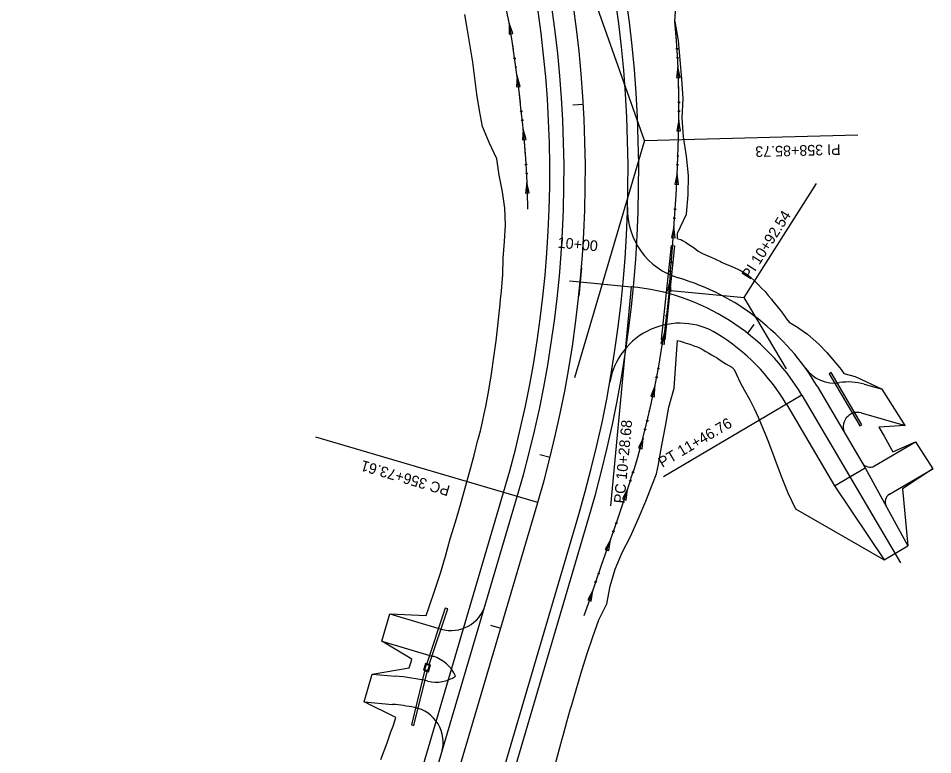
# Model space of a CAD drawing. Extents: x 948761 to 996004, y 1858548 to 1925175.
# Drawn here: x 961025 to 961539, y 1906557 to 1906971 of the extents above; entities that cross this region are included whole.
import ezdxf

# ---------------------------------------------------------------- set-up
doc = ezdxf.new("R2010")
doc.units = 0
for name, color, linetype in [('62', 7, 'Continuous'), ('R_Drainage', 7, 'Continuous'), ('R_Horz Alg', 7, 'Continuous'), ('R_Horz Alg Annot', 7, 'Continuous'), ('R_Proposed Const Limits', 7, 'Continuous'), ('R_Proposed Road', 7, 'Continuous')]:
    doc.layers.add(name, color=color, linetype=linetype)

msp = doc.modelspace()

# ---------------------------------------------------------------- linework, layer by layer
at = {"layer": '62'}
for p, q in [((961301.25, 1906967.91), (961301.21, 1906961.81)), ((961303.3, 1906962.16), (961301.25, 1906967.91)), ((961301.21, 1906961.81), (961303.3, 1906962.16)), ((961396.18, 1906943.39), (961395.38, 1906937.35)), ((961397.49, 1906937.44), (961396.18, 1906943.39)), ((961305.75, 1906938.21), (961305.45, 1906932.12)), ((961307.55, 1906932.39), (961305.75, 1906938.21)), ((961395.38, 1906937.35), (961397.49, 1906937.44)), ((961305.45, 1906932.12), (961307.55, 1906932.39)), ((961396.7, 1906913.36), (961395.53, 1906907.38)), ((961397.65, 1906907.34), (961396.7, 1906913.36)), ((961309.19, 1906908.37), (961308.71, 1906902.29)), ((961310.81, 1906902.5), (961309.19, 1906908.37)), ((961395.53, 1906907.38), (961397.65, 1906907.34)), ((961308.71, 1906902.29), (961310.81, 1906902.5)), ((961395.79, 1906883.33), (961394.42, 1906877.4)), ((961396.53, 1906877.29), (961395.79, 1906883.33)), ((961311.31, 1906878.41), (961310.48, 1906872.38)), ((961312.6, 1906872.46), (961311.31, 1906878.41)), ((961394.42, 1906877.4), (961396.53, 1906877.29)), ((961310.48, 1906872.38), (961312.6, 1906872.46)), ((961393.92, 1906853.36), (961392.5, 1906847.43)), ((961394.61, 1906847.3), (961393.92, 1906853.36)), ((961392.5, 1906847.43), (961394.61, 1906847.3)), ((961391.66, 1906823.41), (961390.25, 1906817.48)), ((961392.36, 1906817.35), (961391.66, 1906823.41)), ((961390.25, 1906817.48), (961392.36, 1906817.35)), ((961388.52, 1906793.54), (961386.46, 1906787.81)), ((961388.55, 1906787.45), (961388.52, 1906793.54)), ((961386.46, 1906787.81), (961388.55, 1906787.45)), ((961383.25, 1906763.97), (961380.96, 1906758.33)), ((961383.03, 1906757.88), (961383.25, 1906763.97)), ((961380.96, 1906758.33), (961383.03, 1906757.88)), ((961376.53, 1906734.7), (961373.94, 1906729.18)), ((961375.99, 1906728.63), (961376.53, 1906734.7)), ((961373.94, 1906729.18), (961375.99, 1906728.63)), ((961367.86, 1906705.96), (961365.06, 1906700.55)), ((961367.08, 1906699.92), (961367.86, 1906705.96)), ((961365.06, 1906700.55), (961367.08, 1906699.92)), ((961358.25, 1906677.5), (961355.26, 1906672.19)), ((961357.26, 1906671.49), (961358.25, 1906677.5)), ((961355.26, 1906672.19), (961357.26, 1906671.49)), ((961348.36, 1906649.14), (961345.43, 1906643.79)), ((961347.44, 1906643.11), (961348.36, 1906649.14)), ((961345.43, 1906643.79), (961347.44, 1906643.11))]:
    msp.add_line(p, q, dxfattribs=at)
for points in [[(961311.79, 1906863.42), (961311.52, 1906872.94), (961311.16, 1906882.44), (961310.67, 1906891.93), (961309.86, 1906901.4), (961308.95, 1906910.85), (961307.92, 1906920.28), (961306.82, 1906929.69), (961305.64, 1906939.07), (961304.35, 1906948.44), (961302.96, 1906957.79), (961301.39, 1906967.1), (961299.69, 1906976.38), (961298.07, 1906984.71)], [(961303.66, 1906953.1), (961302.96, 1906957.79), (961301.39, 1906967.1), (961301.24, 1906967.9)], [(961343.5, 1906634.95), (961346.76, 1906644.41), (961349.98, 1906653.89), (961353.27, 1906663.34), (961356.59, 1906672.79), (961359.91, 1906682.24), (961363.32, 1906692.12), (961366.71, 1906702.29), (961369.6, 1906711.53), (961369.9, 1906712.53), (961371.83, 1906717.69), (961373.29, 1906722.75), (961373.62, 1906723.92), (961376.1, 1906733.11), (961378.73, 1906743.54), (961381.11, 1906754.02), (961383.37, 1906764.54), (961385.39, 1906775.11), (961387.18, 1906785.72), (961388.75, 1906794.86), (961388.75, 1906794.86), (961388.95, 1906796.34), (961390.25, 1906807.03), (961391.32, 1906817.75), (961391.97, 1906828.5), (961392.94, 1906839.22), (961393.71, 1906849.96), (961394.36, 1906860.72), (961395.16, 1906871.48), (961395.74, 1906882.26), (961396.12, 1906893.05), (961396.53, 1906903.86), (961396.72, 1906914.68), (961396.72, 1906925.52), (961396.48, 1906936.35), (961396.02, 1906947.18), (961395.35, 1906958.01), (961394.48, 1906968.82)], [(961395.32, 1906958.4), (961394.48, 1906968.82)], [(961395.32, 1906958.36), (961395.32, 1906958.4)], [(961303.66, 1906953.06), (961303.66, 1906953.1)], [(961396.65, 1906928.4), (961396.48, 1906936.35), (961396.18, 1906943.39)], [(961307.57, 1906923.32), (961306.82, 1906929.69), (961305.75, 1906938.21)], [(961396.65, 1906928.36), (961396.65, 1906928.39)], [(961307.57, 1906923.28), (961307.57, 1906923.32)], [(961396.32, 1906898.36), (961396.53, 1906903.86), (961396.7, 1906913.36)], [(961310.54, 1906893.43), (961309.86, 1906901.4), (961309.19, 1906908.37)], [(961396.32, 1906898.33), (961396.32, 1906898.36)], [(961310.55, 1906893.39), (961310.54, 1906893.43)], [(961394.93, 1906868.36), (961395.16, 1906871.48), (961395.74, 1906882.26), (961395.78, 1906883.34)], [(961311.79, 1906863.42), (961311.52, 1906872.94), (961311.31, 1906878.41)], [(961394.93, 1906868.32), (961394.93, 1906868.36)], [(961392.87, 1906838.39), (961392.94, 1906839.22), (961393.71, 1906849.96), (961393.92, 1906853.36)], [(961392.86, 1906838.36), (961392.87, 1906838.39)], [(961390.39, 1906808.46), (961391.32, 1906817.75), (961391.66, 1906823.41)], [(961390.39, 1906808.42), (961390.39, 1906808.46)], [(961386, 1906778.76), (961387.18, 1906785.72), (961388.52, 1906793.54)], [(961386, 1906778.72), (961386, 1906778.76)], [(961380.05, 1906749.32), (961381.11, 1906754.02), (961383.25, 1906763.97)], [(961380.04, 1906749.28), (961380.05, 1906749.32)], [(961372.57, 1906720.23), (961373.29, 1906722.75), (961373.62, 1906723.92), (961376.1, 1906733.11), (961376.5, 1906734.71)], [(961372.56, 1906720.2), (961372.57, 1906720.23)], [(961363.18, 1906691.71), (961363.32, 1906692.12), (961366.71, 1906702.29), (961367.86, 1906705.96)], [(961363.17, 1906691.67), (961363.18, 1906691.71)], [(961353.27, 1906663.35), (961356.59, 1906672.79), (961358.25, 1906677.5)], [(961353.26, 1906663.31), (961353.27, 1906663.34), (961353.27, 1906663.35)], [(961343.5, 1906634.95), (961346.76, 1906644.41), (961348.36, 1906649.14)]]:
    msp.add_lwpolyline(points, dxfattribs=at)
for centre in [(961395.6, 1906953.39), (961304.36, 1906948.13), (961395.91, 1906948.38), (961305.04, 1906943.16), (961396.68, 1906923.37), (961308.1, 1906918.33), (961396.68, 1906918.36), (961308.64, 1906913.34), (961310.81, 1906888.42), (961395.92, 1906888.34), (961396.1, 1906893.35), (961311.07, 1906883.41), (961394.52, 1906863.35), (961394.19, 1906858.36), (961392.38, 1906833.4), (961391.92, 1906828.4), (961389.78, 1906803.48), (961389.17, 1906798.5), (961385.11, 1906773.82), (961384.17, 1906768.89), (961378.9, 1906744.43), (961377.69, 1906739.57), (961370.97, 1906715.48), (961369.32, 1906710.75), (961361.51, 1906686.97), (961359.87, 1906682.24), (961351.59, 1906658.62), (961349.94, 1906653.89)]:
    msp.add_circle(centre, 0.375, dxfattribs=at)
at = {"layer": 'R_Drainage'}
for p, q in [((961392.27, 1906842.88), (961386.73, 1906790.17)), ((961394.26, 1906842.67), (961388.72, 1906789.96)), ((961392.27, 1906842.88), (961394.26, 1906842.67)), ((961386.73, 1906790.17), (961388.72, 1906789.96)), ((961482.21, 1906771.52), (961481.13, 1906770.88)), ((961481.13, 1906770.88), (961498.41, 1906741.6)), ((961499.48, 1906742.23), (961482.21, 1906771.52)), ((961498.41, 1906741.6), (961499.48, 1906742.23)), ((961265.39, 1906639.14), (961254.78, 1906607.42)), ((961256.22, 1906607), (961266.81, 1906638.67)), ((961266.81, 1906638.67), (961265.39, 1906639.14)), ((961253.95, 1906604.54), (961246.34, 1906573.49)), ((961247.8, 1906573.13), (961255.39, 1906604.11)), ((961246.34, 1906573.49), (961247.8, 1906573.13))]:
    msp.add_line(p, q, dxfattribs=at)
for points in [[(961254.21, 1906608.11), (961253.08, 1906604.27), (961255.96, 1906603.43), (961257.09, 1906607.26)], [(961254.55, 1906607.49), (961253.7, 1906604.61), (961255.62, 1906604.05), (961256.47, 1906606.92)]]:
    msp.add_lwpolyline(points, close=True, dxfattribs=at)
at = {"layer": 'R_Horz Alg'}
for p, q in [((961341.25, 1906822.46), (961369.8, 1906819.77)), ((961465.8, 1906758.76), (961521.2, 1906664.7)), ((961044.57, 1905773.69), (961317.38, 1906698.54))]:
    msp.add_line(p, q, dxfattribs=at)
for centre, radius, start, end in [((960689.32, 1906883.81), 654.81, 343.56518, 19.46478), ((961358.09, 1906695.32), 125, 30.4985, 84.6244)]:
    msp.add_arc(centre, radius, start, end, dxfattribs=at)
at = {"layer": 'R_Horz Alg Annot'}
for p, q in [((961377.39, 1906902), (961338.2, 1907012.88)), ((961377.39, 1906902), (961338.05, 1906768.62)), ((961392.13, 1906817.67), (961433.38, 1906813.79)), ((961457.08, 1906773.57), (961433.38, 1906813.79))]:
    msp.add_line(p, q, dxfattribs=at)
for points in [[(961337.01, 1906921.99), (961343, 1906922.35)], [(961377.39, 1906902), (961497.35, 1906905.18)], [(961433.38, 1906813.79), (961474.04, 1906877.76)], [(961342, 1906830.42), (961340.5, 1906814.5)], [(961335.28, 1906823.02), (961341.25, 1906822.46)], [(961369.8, 1906819.77), (961358.21, 1906696.57)], [(961438.86, 1906798.46), (961435.17, 1906793.73)], [(961465.8, 1906758.76), (961388.05, 1906712.97)], [(961317.38, 1906698.54), (961192.69, 1906735.32)], [(961318.51, 1906725.46), (961324.33, 1906724)], [(961497.99, 1906715.93), (961492.82, 1906712.89)], [(961290.8, 1906629.64), (961296.55, 1906627.94)]]:
    msp.add_lwpolyline(points, dxfattribs=at)
at = {"layer": 'R_Proposed Const Limits'}
for points in [[(961394.48, 1906968.82), (961395.16, 1906979.86), (961393.56, 1906990.62), (961388.58, 1906999.72), (961387.9, 1907000.7), (961383.63, 1907009.7), (961383.63, 1907009.7), (961383.13, 1907010.82), (961378.68, 1907020.92)], [(961299.15, 1906854.51), (961298.89, 1906863.9), (961297.6, 1906873.18), (961295.68, 1906882.48), (961294.29, 1906891.72), (961289.96, 1906900.84), (961286.23, 1906909.86), (961284.7, 1906918.91), (961283.1, 1906927.93), (961282.06, 1906936.96), (961280.85, 1906945.97), (961279.35, 1906954.94), (961277.79, 1906963.89), (961276.29, 1906972.83)], [(961396.05, 1906846.72), (961395.86, 1906846.76), (961395.95, 1906849.86), (961400.92, 1906860.5), (961401.88, 1906871.36), (961402.15, 1906882.24), (961400.96, 1906893.11), (961399.31, 1906903.94), (961398.52, 1906914.76), (961399, 1906925.65), (961398.4, 1906936.49), (961397.49, 1906947.31), (961396.38, 1906958.11), (961394.62, 1906968.84)], [(961234.14, 1906635.93), (961254.62, 1906635.01), (961256.39, 1906639.79), (961259.51, 1906649.29), (961262.62, 1906658.8), (961265.44, 1906668.4), (961268.22, 1906678.01), (961271.05, 1906687.59), (961273.95, 1906697.17), (961276.6, 1906706.81), (961279.14, 1906716.06), (961281.57, 1906725.11), (961283.68, 1906733.76), (961283.79, 1906734.2), (961285.2, 1906738.77), (961286.31, 1906743.78), (961287.27, 1906748.36), (961288.13, 1906752.42), (961289.83, 1906761.62), (961291.36, 1906770.86), (961292.73, 1906780.11), (961293.91, 1906789.39), (961294.86, 1906797.74), (961295.89, 1906806.67), (961296.03, 1906807.96), (961296.48, 1906812.61), (961296.94, 1906817.25), (961297.68, 1906826.56), (961297.99, 1906835.9), (961298.67, 1906845.2), (961299.15, 1906854.51)], [(961396.05, 1906846.72), (961397.82, 1906846.28), (961398.8, 1906845.68), (961400.32, 1906844.73), (961402.79, 1906843.15), (961405.23, 1906841.55), (961407.59, 1906839.83), (961409.51, 1906838.67), (961410.04, 1906838.45), (961412.59, 1906837.39), (961415.12, 1906836.26), (961417.62, 1906835.09), (961420.1, 1906833.87), (961420.58, 1906833.62), (961422.61, 1906832.73), (961425.2, 1906831.75), (961427.73, 1906830.64), (961430.23, 1906829.44), (961431.72, 1906828.69), (961432.69, 1906828.17), (961435.04, 1906826.7), (961437.21, 1906824.96), (961439.26, 1906823.04), (961441.24, 1906821.04), (961441.25, 1906821.03), (961443.19, 1906819.05), (961445.12, 1906817.06), (961446.88, 1906814.87), (961448.67, 1906812.76), (961449.39, 1906811.89), (961450.42, 1906810.63), (961452.13, 1906808.49), (961453.8, 1906806.34), (961455.42, 1906804.16), (961456.71, 1906802.38), (961457.01, 1906801.97)], [(961457.01, 1906801.97), (961458.67, 1906799.88), (961463.28, 1906797.01), (961466.03, 1906795.15), (961468.9, 1906793.1), (961475.36, 1906787.54), (961479.93, 1906782.88), (961487.02, 1906774.45), (961487.83, 1906773.34), (961489.44, 1906771.08), (961495.74, 1906769.35), (961510.96, 1906762.14)], [(961348.32, 1906623.1), (961351.74, 1906632.52), (961356.27, 1906641.61), (961358.1, 1906651.49), (961360.93, 1906661.08), (961364.83, 1906670.36), (961369.42, 1906679.43), (961373.73, 1906689.16), (961378.09, 1906699.24), (961381.73, 1906708.45), (961382.13, 1906709.46), (961384.05, 1906714.71), (961385.16, 1906719.95), (961385.38, 1906721.17), (961387.17, 1906730.69), (961389.25, 1906741.4), (961391.02, 1906752.16), (961393.97, 1906762.72), (961394.76, 1906773.65), (961395.55, 1906784.54), (961395.88, 1906789.47)], [(961395.88, 1906789.47), (961397.58, 1906789.12), (961397.99, 1906788.99), (961399.76, 1906788.44), (961400.12, 1906788.32), (961401.54, 1906787.86), (961403.32, 1906787.26), (961405.09, 1906786.65), (961406.87, 1906786.01), (961407.94, 1906785.62), (961408.63, 1906785.33), (961410.26, 1906784.4), (961411.88, 1906783.46), (961413.5, 1906782.5), (961415.1, 1906781.53), (961415.11, 1906781.52), (961416.71, 1906780.54), (961418.31, 1906779.55), (961419.9, 1906778.54), (961421.48, 1906777.51), (961422.12, 1906777.08), (961423.05, 1906776.45), (961424.69, 1906775.48), (961426.46, 1906774.63)], [(961426.46, 1906774.63), (961427.85, 1906773.33), (961429.13, 1906770.54), (961431.1, 1906765.9), (961433.43, 1906761.81), (961436.58, 1906756.17), (961439.04, 1906751.29), (961441.3, 1906746.39), (961442.61, 1906743.22), (961445.12, 1906737.02), (961447.04, 1906732.35), (961450.69, 1906722.89), (961454.16, 1906713.33), (961457.93, 1906703.94), (961462.29, 1906694.91), (961512.16, 1906666.25)], [(961523.85, 1906741.87), (961509.08, 1906740.92), (961512.11, 1906735.86), (961516.85, 1906727.04), (961529.7, 1906732.66)], [(961539.35, 1906717.46), (961522.43, 1906706.11), (961525.45, 1906674.08)], [(961318.87, 1906474.81), (961307.38, 1906499.64), (961318.37, 1906517.25), (961321.02, 1906526.89), (961323.37, 1906536.62), (961325.03, 1906543.03), (961325.91, 1906546.3), (961328.5, 1906555.96), (961331.1, 1906565.62), (961331.62, 1906567.55), (961333.74, 1906575.27), (961335.67, 1906582), (961336.49, 1906584.89), (961339.24, 1906594.5), (961339.83, 1906596.41), (961342.19, 1906604.05), (961345.16, 1906613.6), (961348.32, 1906623.1)], [(961224.3, 1906602.13), (961245.12, 1906605.58), (961245.97, 1906608.46), (961246.6, 1906610.55), (961229.67, 1906620.56)], [(961229.16, 1906553.99), (961232.64, 1906563.39), (961234.87, 1906569.62), (961236.02, 1906572.81), (961237.51, 1906577.63), (961219.73, 1906586.47)]]:
    msp.add_lwpolyline(points, dxfattribs=at)
at = {"layer": 'R_Proposed Road'}
for p, q in [((961474.41, 1906763.84), (961501.43, 1906717.96)), ((961500.89, 1906764.99), (961510.96, 1906762.14)), ((961523.85, 1906741.87), (961510.96, 1906762.14)), ((961457.18, 1906753.69), (961484.2, 1906707.81)), ((961499.23, 1906748.83), (961523.85, 1906741.87)), ((961506.59, 1906719.05), (961529.7, 1906732.66)), ((961529.7, 1906732.66), (961539.35, 1906717.46)), ((961484.2, 1906707.81), (961501.43, 1906717.96)), ((961501.43, 1906717.96), (961525.45, 1906674.08)), ((961515.06, 1906703.15), (961539.35, 1906717.46)), ((961025.38, 1905779.35), (961298.19, 1906704.2)), ((961484.2, 1906707.81), (961512.16, 1906666.25)), ((961033.06, 1905777.09), (961305.87, 1906701.94)), ((961067.59, 1905766.9), (961340.4, 1906691.75)), ((961073.34, 1905765.2), (961346.15, 1906690.06)), ((961512.16, 1906666.25), (961525.45, 1906674.08)), ((961229.67, 1906620.56), (961234.14, 1906635.93)), ((961234.14, 1906635.93), (961263.03, 1906627.4)), ((961229.67, 1906620.56), (961258.5, 1906612.06)), ((961219.73, 1906586.47), (961224.3, 1906602.13)), ((961224.3, 1906602.13), (961237.15, 1906601)), ((961219.73, 1906586.47), (961235.76, 1906585.07))]:
    msp.add_line(p, q, dxfattribs=at)
for centre, radius, start, end in [((960689.32, 1906883.81), 678.81, 343.56518, 19.46478), ((960689.32, 1906883.81), 684.81, 343.56518, 19.46478), ((960689.32, 1906883.81), 634.81, 343.56518, 19.46478), ((960689.32, 1906883.81), 642.81, 343.56518, 19.46478), ((961407.83, 1906863.1), 40, 178.3498, 253.4862), ((961358.09, 1906695.32), 135, 30.4985, 73.4862), ((961397.26, 1906759.28), 40, 58.5131, 170.0239), ((961358.09, 1906695.32), 115, 30.4985, 58.5131), ((961484.05, 1906785.66), 20, 215.6466, 278.5206), ((961491.9, 1906733.24), 33, 74.1969, 98.6512), ((961497.07, 1906741.13), 8, 74.0665, 210.4985), ((961504.06, 1906723.36), 5, 210.4985, 300.4985), ((961517.6, 1906698.84), 5, 120.4985, 208.6882), ((961268.69, 1906646.59), 20, 253.5652, 343.5652), ((961252.84, 1906592.88), 20, 23.6058, 73.5652), ((961225.58, 1906468.51), 133, 76.9492, 85.006), ((961260.13, 1906617.56), 20, 256.9492, 303.5246), ((961225.58, 1906468.51), 117, 78.9075, 85.006), ((961244.24, 1906563.7), 20, 343.5652, 78.9075)]:
    msp.add_arc(centre, radius, start, end, dxfattribs=at)

# ---------------------------------------------------------------- texts
at = {"layer": 'R_Horz Alg'}
for rotation, p in [(354.6244, (961340.78, 1906822)), (354.6244, (961369.33, 1906819.32)), (300.4985, (961465.15, 1906758.88)), (73.5652, (961317.86, 1906698.4)), (300.4985, (961520.55, 1906664.82))]:
    msp.add_text('+', height=1, rotation=rotation, dxfattribs=at).set_placement(p)
at = {"layer": 'R_Horz Alg Annot'}
for s, rotation, p in [('PI 358+85.73', 181.515, (961487.49, 1906899.91)), ('PI 10+92.54', 57.5614, (961436.62, 1906823.42)), ('10+00', 354.6244, (961328.36, 1906841.75)), ('PT 11+46.76', 30.4985, (961387.38, 1906717.9)), ('PC 10+28.68', 84.6244, (961366.06, 1906697.79)), ('PC 356+73.61', 163.5652, (961268.48, 1906707.75))]:
    msp.add_text(s, height=6, rotation=rotation, dxfattribs=at).set_placement(p)

doc.saveas('drawing.dxf')
